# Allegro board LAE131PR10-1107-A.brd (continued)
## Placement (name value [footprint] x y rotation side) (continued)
RD14  -  [R_0402]  79.17 25.38 270 top
RD15  -  [R_0402]  170.27 27.54 90 top
RD16  -  [R_0402]  171.15 28.45 270 top
RD17  -  [R_0402]  172.02 28.45 270 top
RD18  -  [R_0402]  174.74 27.27 270 top
RD19  -  [R_0402]  88.61 62.61 0 bottom
RD20  -  [R_0402]  189.49 28.26 0 top
RD21  -  [R0402_0OHM]  190.4 27.37 180 top
RD22  -  [R0402_0OHM]  196.36 29.76 180 top
RD23  -  [R_0402]  195.43 28.87 0 top
RD24  -  [R_0402]  170.56 24.8 90 top
RD25  -  [R0402_0OHM]  169.67 25.83 270 top
RD26  -  [R0603_0OHM]  190.1 29.23 90 top
RD27  -  [R_0402]  80.06 25.38 270 top
RD28  -  [R_0402]  168.64 29.04 270 top
RD29  -  [R_0402]  167.1 28.12 90 top
RD30  -  [R_0402]  166.21 28.12 90 top
RD31  -  [R_0402]  162.37 28.12 90 top
RE5  -  [R_0402]  262.83 49.22 90 top
RE6  -  [R_0402]  279.4 61.5 180 top
RE8  -  [R_0402]  257 35.71 0 top
RE10  -  [R_0402]  274.94 35.21 270 top
RE11  -  [R_0402]  262.7 34.58 270 top
RE12  -  [R_0402]  275.96 34.23 0 top
RE13  -  [R_0402]  277.84 55.64 90 top
RE14  -  [R_0402]  278.74 56.57 270 top
RE15  -  [R_0402]  279.43 57.91 180 top
RE16  -  [R_0402]  278.51 58.82 0 top
RE17  -  [R_0402]  279.43 59.71 180 top
RE18  -  [R_0402]  278.49 60.6 0 top
RE20  -  [R_0402]  263.59 34.58 270 top
RE21  -  [R_0402]  255.02 34.58 90 top
RE25  -  [R_0402]  279.78 46.21 0 top
RE26  -  [R_0402]  281.64 45.27 90 top
RE30  -  [R0402_0OHM]  296.48 73.89 90 bottom
RE31  -  [R_0402]  250.99 30.17 90 top
RE32  -  [R0402_0OHM]  259.91 32.9 90 top
RE33  -  [R_0402]  250.05 31.15 90 top
RE34  -  [R0402_0OHM]  239.3 38.92 90 top
RE35  -  [R_0402]  273.22 49.14 90 top
RE37  -  [R_0402]  275.96 36.01 0 top
RE38  -  [R_0402]  272.33 49.14 90 top
RE43  -  [R_0402]  275.96 35.12 0 top
RE48  -  [R_0402]  184.05 69.75 90 bottom
RE51  -  [R_0402]  183.1 69.75 90 bottom
RE55  -  [R_0402]  261.81 34.58 270 top
RE56  -  [R_0402]  268.1 34.58 270 top
RE57  -  [R_0402]  261.37 32.24 270 top
RE58  -  [R_0402]  260.94 33.66 90 top
RE59  -  [R0402_0OHM]  271.5 51.1 90 top
RE60  -  [R_0402]  270.98 49.19 90 top
RE63  -  [R_0402]  265.86 51.39 0 top
RE64  -  [R_0402]  274.91 30.46 270 top
RE65  -  [R_0402]  264.94 51.39 180 top
RE67  -  [R_0402]  284.51 28.14 270 top
RE68  -  [R_0402]  281.4 30.28 90 top
RE69  -  [R_0402]  241.63 39.95 270 bottom
RE70  -  [R_0402]  240.17 36.24 180 bottom
RE71  -  [R_0402]  305.02 73.82 180 bottom
RE72  -  [R_0402]  301.22 76.52 270 bottom
RE73  -  [R_0402]  298.5 76.56 270 bottom
RE74  -  [R_0402]  297.58 76.55 270 bottom
RE75  -  [R_0402]  300.34 76.52 270 bottom
RE77  -  [R_0402]  263.01 52.3 90 top
RE79  -  [R_0402]  270.11 50.12 270 top
RE83  -  [R_0402]  267.85 49.22 90 top
RE84  -  [R_0402]  266.96 49.22 90 top
RE85  -  [R_0402]  266.07 49.22 90 top
RE86  -  [R_0402]  297.41 73.88 90 bottom
RE90  -  [R0402_0OHM]  241.1 35.31 90 bottom
RE91  -  [R_0402]  268.78 27.35 90 top
RE92  -  [R_0402]  262.74 28.4 0 top
RE93  -  [R_0201]  259.18 38.58 180 top
RE94  -  [R_0402]  255.46 39.93 90 top
RE95  -  [R_0402]  278.54 42.89 180 top
RE98  -  [R_0402]  278.65 35.65 180 top
RE274  -  [R_0402]  174.06 49.22 180 top
RE275  -  [R0402_0OHM]  174.98 48.32 180 top
RE280  -  [R_0402]  254.4 52.28 270 top
RE288  -  [R_0402]  268.66 51.02 90 top
RE290  -  [R0402_0OHM]  258.12 33.32 270 top
RE292  -  [R_0402]  255.3 51.35 90 top
RE300  -  [R_0402]  258.07 57.75 90 top
RE301  -  [R_0402]  261.95 49.74 90 top
RE302  -  [R_0402]  252.78 35.4 0 top
RE303  -  [R_0402]  252.78 34.45 0 top
RE304  -  [R_0402]  260.12 55.43 0 top
RE306  -  [R_0402]  299.39 76.52 270 bottom
RE308  -  [R_0402]  271.52 52.95 0 top
RE312  -  [R_0402]  274.94 32.95 270 top
RE313  -  [R_0402]  274.03 32.94 270 top
RE314  -  [R_0402]  265.99 32.66 0 top
RE318  -  [R0402_0OHM]  267.79 28.21 270 top
RE324  -  [R_0402]  265.95 28.23 270 top
RE337  -  [R_0402]  271.5 31.2 90 top
RE338  -  [R_0402]  278.53 41.99 180 top
RE339  -  [R_0402]  278.68 38.31 180 top
RE340  -  [R_0402]  276.58 31.99 0 top
RE341  -  [R_0402]  271.11 33.56 90 top
RE342  -  [R_0402]  269.37 32.31 0 top
RE343  -  [R_0402]  263.59 30.26 270 top
RE348  -  [R_0402]  240.21 39.85 270 top
RE349  -  [R_0402]  278.73 39.25 180 top
RE350  -  [R_0402]  254 40.16 270 top
RE360  -  [R0402_0OHM]  277.61 41.1 0 top
RE361  -  [R_0402]  262.7 31.44 90 top
RE362  -  [R_0402]  262.7 30.26 270 top
RE363  -  [R_0402]  269.03 34.58 270 top
RE364  -  [R0402_0OHM]  278.56 34.69 0 top
RE365  -  [R_0402]  250.13 41.37 0 top
RE366  -  [R_0402]  249.19 39.39 180 top
RE367  -  [R_0402]  233.89 38.89 180 top
RE368  -  [R_0402]  249.25 38.37 180 top
RE369  -  [R_0402]  235.66 38.58 180 top
RE370  -  [R_0402]  249.19 37.42 180 top
RE371  -  [R_0402]  235.54 37.24 180 top
RE372  -  [R_0402]  249.25 36.47 180 top
RE373  -  [R_0402]  233.76 37.24 180 top
RE374  -  [R_0402]  233.97 45.3 180 bottom
RE375  -  [R_0402]  226.94 37.19 0 bottom
RE376  -  [R_0402]  245.54 38.04 180 bottom
RE377  -  [R_0402]  247.27 36.56 270 top
RE505  -  [R_0402]  284.67 33.57 270 top
RE506  -  [R0402_0OHM]  280.34 40.67 90 top
RE507  -  [R_0402]  259.27 39.49 180 top
RE508  -  [R_0402]  259.01 32.04 0 top
RE512  -  [R_0402]  279.85 38.88 90 top
RE513  -  [R_0402]  280.74 38.88 90 top
RE514  -  [R_0402]  257.24 40.85 270 top
RE515  -  [R0402_0OHM]  256.34 40.85 270 top
RE524  -  [R_0402]  278.07 54.39 270 top
RE525  -  [R_0402]  277.13 54.39 270 top
RE526  -  [R_0402]  255.74 48.52 0 top
RE530  -  [R_0402]  257.58 86.07 0 top
RE532  -  [R_0402]  280.71 45.22 270 top
RE536  -  [R_0402]  237.12 40.67 90 top
RE537  -  [R_0402]  238.05 41.59 270 top
RE539  -  [R_0402]  276.66 51.15 0 top
RI13  -  [R_0402]  291.77 67.85 270 top
RI14  -  [R_0402]  294.79 71.62 180 top
RI27  -  [R_0402]  275.72 68.15 180 top
RI28  -  [R_0402]  275.72 69.03 180 top
RI29  -  [R_0402]  275.74 70.05 180 top
RI30  -  [R_0402]  275.74 70.92 180 top
RI47  -  [R_0402]  263.28 60.56 90 top
RI48  -  [R_0402]  264.16 60.56 90 top
RI49  -  [R_0402]  290.25 33.36 90 bottom
RI50  -  [R_0402]  291.14 33.36 90 bottom
RL1  -  [R_0402]  273.59 99.33 90 top
RL2  -  [R_0402]  272.06 99.38 90 top
RL3  -  [R0402_0OHM]  273.56 86.58 270 top
RL4  -  [R_0402]  270.54 92.08 270 top
RL5  -  [R_0402]  269.69 89.4 270 top
RL6  -  [R_0402]  268.8 89.4 270 top
RL7  -  [R0402_0OHM]  271.21 88.49 90 top
RL8  -  [R0603_0OHM]  270.64 87.34 180 top
RL9  -  [R_0402]  272.1 89.4 270 top
RL11  -  [R_0402]  277.55 88.93 0 top
RL12  -  [R_0402]  275.08 99.41 90 top
RL13  -  [R_0402]  281.89 89.35 0 top
RL14  -  [R_0402]  296.8 78.45 0 top
RL15  -  [R_0402]  303.15 90.8 0 top
RL16  -  [R_0402]  303.15 89.5 0 top
RL17  -  [R_0402]  303.19 83.25 0 top
RL18  -  [R_0402]  303.19 82.01 0 top
RL19  -  [R_0402]  295.28 82.52 180 top
RL20  -  [R_0402]  298.32 82.26 90 top
RL29  -  [R_0402]  295.35 86.56 180 top
RL30  -  [R_0402]  296.32 85.41 270 top
RL34  -  [R0402_0OHM]  278.46 88.04 180 top
RL70  -  [R_0402]  281.87 88.11 0 top
RL71  -  [R_0603]  281.97 90.48 0 top
RL72  -  [R_0603]  281.97 91.69 0 top
RL73  -  [R_0603]  281.97 92.89 0 top
RL74  -  [R_0603]  281.97 94.1 0 top
RL75  -  [R_0603]  281.97 95.31 0 top
RL76  -  [R_0603]  281.97 96.51 0 top
RL77  -  [R_0603]  281.97 97.72 0 top
RL78  -  [R_0603]  281.97 98.93 0 top
RN37  -  [R_0402]  24.78 16.92 180 top
RN99  -  [R0402_0OHM]  21.29 19.02 0 bottom
RN100  -  [R_0402]  41.02 19.28 90 top
RPC1  -  [RP_0804_8P4R]  176.59 84.44 0 bottom
RPC3  -  [RP_0804_8P4R]  147.04 99.8 90 bottom
RPC4  -  [RP_0804_8P4R]  163.03 86.28 0 bottom
RPE7  -  [RP_0804_8P4R]  303.82 75.66 90 bottom
RPE9  -  [RP_0804_8P4R]  276.67 46.87 0 top
RPE10  -  [RP_0804_8P4R]  276.67 49.85 0 top
RPE11  -  [RP_0804_8P4R]  269.76 30.92 270 top
RPE12  -  [RP_0804_8P4R]  274.95 43.69 0 top
RR3  -  [R_0402]  297.88 56.5 270 top
RR4  -  [R_0402]  292.56 50.39 180 top
RR5  -  [R0402_0OHM]  301.41 48.71 0 top
RR6  -  [R0402_0OHM]  301.42 50.48 0 top
RR7  -  [R0402_0OHM]  301.42 51.35 0 top
RR8  -  [R0402_0OHM]  301.87 52.23 0 top
RR9  -  [R0402_0OHM]  300.05 47.75 270 top
RR10  -  [R0402_0OHM]  300.94 47.73 270 top
RR19  -  [R_0402]  294.45 54.5 90 top
RT1  -  [R_0402]  23.88 72.99 90 bottom
RT2  -  [R_0402]  35.05 74.26 0 top
RT3  -  [R_0402]  35.05 73.25 0 top
RT4  -  [R_0402]  35.05 72.23 0 top
RT5  -  [R_0402]  33.24 82.35 0 bottom
RT6  -  [R_0402]  32.54 80.57 0 bottom
RT7  -  [R_0402]  32.54 81.46 0 bottom
RT8  -  [R_0402]  33.24 83.24 0 bottom
RT9  -  [R0402_0OHM]  35.97 75.28 180 top
RT10  -  [R_0402]  35.05 71.21 0 top
RT11  -  [R_0402]  24.68 80.08 270 bottom
RT12  -  [R_0402]  34.01 77.67 270 top
RT13  -  [R_0402]  34.9 77.67 270 top
RT14  -  [R_0402]  38.58 79.55 90 top
RT15  -  [R_0402]  38.58 79.55 90 bottom
RT16  -  [R_0402]  27.28 77.6 270 bottom
RT17  -  [R_0402]  25.63 77.6 270 top
RT18  -  [R_0402]  30.14 75.8 90 top
RT19  -  [R_0402]  31.35 75.8 90 top
RT20  -  [R_0402]  26.52 77.6 270 top
RT21  -  [R_0402]  21.13 83.45 180 top
RT22  -  [R_0402]  21.13 84.34 180 top
RT23  -  [R_0402]  28.42 81.6 270 bottom
RT24  -  [R_0402]  38.46 77.67 270 top
RT25  -  [R_0402]  25.5 77.6 270 bottom
RT26  -  [R_0402]  24.69 81.84 180 bottom
RT27  -  [R_0402]  24.61 77.6 270 bottom
RT28  -  [R_0402]  32.23 77.67 270 top
RT29  -  [R_0402]  34.14 84.12 90 bottom
RT30  -  [R_0402]  37.57 77.67 270 top
RT31  -  [R_0402]  18.96 83.55 90 top
RT32  -  [R_0402]  21.13 85.23 180 top
RT33  -  [R_0402]  27.47 77.6 270 top
RT34  -  [R_0402]  32.07 91 180 bottom
RT35  -  [R_0402]  35.03 84.12 90 bottom
RT36  -  [R_0402]  24.74 77.6 270 top
RT37  -  [R_0402]  36.01 81.83 270 top
RT38  -  [R_0402]  33.25 89.2 90 bottom
RT39  -  [R_0402]  27.08 84.84 0 bottom
RT40  -  [R0402_0OHM]  22.21 93.61 0 top
RT41  -  [R_0402]  26.27 90.88 0 bottom
RT42  -  [R_0402]  25.41 89.42 180 bottom
RT48  -  [R_0603]  23.62 73.12 270 top
RT49  -  [R_0603]  22.35 73.12 90 top
RT50  -  [R_0402]  28.12 50.43 180 top
RT51  -  [R_0402]  25.05 49.48 0 top
RT52  -  [R_0402]  25.05 50.43 0 top
RT53  -  [R_0402]  25.05 52.34 0 top
RT54  -  [R0402_0OHM]  28.12 51.45 180 top
RT55  -  [R0402_0OHM]  28.12 52.34 180 top
RT56  -  [R0402_0OHM]  25.05 51.38 0 top
RT57  -  [R0402_0OHM]  25.05 48.53 0 top
RT58  -  [R0402_0OHM]  39.21 66.22 180 bottom
RT59  -  [R0402_0OHM]  38.29 62.86 0 bottom
RT60  -  [R0402_0OHM]  34.06 61.32 180 top
RT63  -  [R0402_0OHM]  29.15 66.44 90 top
RT64  -  [R_0402]  33.15 59.54 0 top
RT65  -  [R_0402]  33.15 58.65 0 top
RT66  -  [R_0402]  38.86 63.72 90 top
RT67  -  [R_0402]  37.85 63.72 90 top
RT68  -  [R_0402]  33.15 60.43 0 top
RT69  -  [R_0402]  33.66 65.63 0 top
RT70  -  [R0402_0OHM]  30.1 69.2 270 top
RT71  -  [R_0402]  28.44 58.07 0 bottom
RT72  -  [R0402_0OHM]  26.81 55.77 90 top
RT73  -  [R0402_0OHM]  28.44 59.02 0 bottom
RT74  -  [R_0402]  27.56 57.36 90 bottom
RT75  -  [R_0402]  26.24 54.51 180 top
RT76  -  [R_0402]  25.12 62.59 180 bottom
RT81  -  [R_0402]  28.7 67.2 90 bottom
RT82  -  [R_0402]  27.82 67.2 90 bottom
RT83  -  [R0402_0OHM]  27.8 66.33 0 bottom
RT84  -  [R_0402]  26.04 66.31 90 bottom
RT85  -  [R_0402]  25.15 66.31 90 bottom
RT86  -  [R_0402]  28.64 56.69 270 top
RT87  -  [R0402_0OHM]  22.13 63.25 0 top
RT88  -  [R0402_0OHM]  22.13 62.36 0 top
RT89  -  [R_0402]  22.33 62.4 90 bottom
RT90  -  [R_0402]  23.23 62.39 90 bottom
RT92  -  [R0402_0OHM]  22.21 65.41 0 top
RT93  -  [R0402_0OHM]  22.21 66.3 0 top
RT95  -  [R_0402]  24.84 67.6 180 top
RT96  -  [R_0402]  25.71 67.6 0 top
RT97  -  [R_0402]  28.4 53.63 180 top
RT98  -  [R_0402]  26.24 53.63 180 top
RT99  -  [R0402_0OHM]  27.48 54.51 0 top
RT100  -  [R_0402]  26.93 66.31 90 bottom
RT101  -  [R_0402]  33.14 61.37 0 bottom
RT103  -  [R_0402]  23.65 56.94 180 top
RT104  -  [R0402_0OHM]  23.64 58.9 180 top
RT105  -  [R0402_0OHM]  23.64 57.82 180 top
RT106  -  [R_0402]  29.66 66.31 90 bottom
RT107  -  [R_0402]  33.14 62.26 0 bottom
RT108  -  [R0402_0OHM]  23.67 60.03 180 top
RT109  -  [R0402_0OHM]  23.67 60.92 180 top
RT110  -  [R_0402]  27.76 56.69 270 top
RT111  -  [R_0402]  18.93 94.91 0 top
RT120  -  [R0402_0OHM]  15.59 89.84 180 top
RT121  -  [R0402_0OHM]  15.59 88.95 180 top
RT122  -  [R0402_0OHM]  14.68 89.84 0 bottom
RT123  -  [R0402_0OHM]  14.68 88.95 0 bottom
RT124  -  [R_0402]  33.12 77.67 270 top
RT125  -  [R_0402]  35.79 77.67 270 top
RT126  -  [R_0402]  37.7 79.55 90 top
RT127  -  [R_0402]  37.7 79.55 90 bottom
RT128  -  [R_0402]  37.33 82.14 315 bottom
RT129  -  [R_0402]  29.31 81.6 270 bottom
RT336  -  [R_0402]  38.48 82.27 315 bottom
RT337  -  [R_0402]  30.2 81.6 270 bottom
RT338  -  [R_0402]  36.68 77.67 270 top
RT339  -  [R_0402]  33.14 60.48 0 bottom
RT341  -  [R0402_0OHM]  38.6 78.67 180 top
RT342  -  [R0402_0OHM]  38.6 78.67 180 bottom
RT371  -  [R_0402]  35.79 77.67 270 bottom
RT372  -  [R_0402]  26.39 77.6 270 bottom
RT377  -  [R_0402]  26.04 61.68 90 bottom
RT391  -  [R_0402]  150.55 102.51 90 bottom
RT392  -  [R0402_0OHM]  25.97 79.74 270 bottom
RT393  -  [R_0402]  17.03 94.34 180 top
RV1  -  [R_0402]  67.44 113.38 90 top
RV2  -  [R_0402]  66.92 116.97 0 top
RV3  -  [R_0402]  73.41 107.66 180 top
RV4  -  [R_0402]  59.31 104.49 0 top
RV5  -  [R_0402]  59.57 102.71 180 top
RV6  -  [R_0402]  98.94 109.75 90 top
RV7  -  [R_0402]  69.19 117.32 0 top
RV8  -  [R_0402]  93.03 116.34 270 top
RV10  -  [R_0402]  16.51 61.8 180 top
RV11  -  [R_0402]  16.51 62.68 180 top
RV12  -  [R_0402]  16.5 65.56 180 top
RV13  -  [R_0402]  16.5 66.44 180 top
RV14  -  [R_0402]  16.51 63.77 180 top
RV15  -  [R_0402]  16.51 64.65 180 top
RV16  -  [R_0402]  16.54 67.48 180 top
RV17  -  [R_0402]  16.54 68.36 180 top
RV18  -  [R_0402]  18.35 72.38 270 top
RV19  -  [R_0402]  19.32 71.47 90 top
RV20  -  [R_0402]  18.76 74.9 270 top
RV21  -  [R_0402]  14.57 74.66 90 top
RV22  -  [R_0402]  16.89 71.39 180 bottom
RV23  -  [R_0402]  16.89 70.16 180 bottom
RV26  -  [R_0402]  15.38 62.76 270 bottom
RV29  -  [R_0402]  15.36 66.49 270 bottom
RV32  -  [R_0402]  15.36 64.69 270 bottom
RV35  -  [R_0402]  15.37 68.29 270 bottom
RV70  -  [R_0402]  102.24 106.33 270 bottom
RV71  -  [R_0402]  104.05 106.33 270 bottom
RV73  -  [R_0402]  108.08 113 90 top
RV74  -  [R_0402]  103.71 112.64 0 top
RV76  -  [R_0402]  103.18 106.33 270 bottom
RV77  -  [R_0402]  104.98 106.33 270 bottom
RV79  -  [R_0402]  120.78 111.6 90 bottom
RV80  -  [R_0402]  123.57 111.52 90 bottom
RV81  -  [R_0402]  120.78 110.58 270 bottom
RV82  -  [R_0402]  121.77 110.53 0 bottom
RV83  -  [R_0402]  121.81 108.68 90 bottom
RV84  -  [R_0402]  122.81 109.19 0 bottom
RV85  -  [R_0402]  121.27 107.38 270 bottom
RV87  -  [R_0402]  115.22 105.08 0 top
RV88  -  [R_0402]  114.3 105.12 180 top
RV89  -  [R_0402]  110.53 104.9 270 bottom
RV90  -  [R_0402]  122.81 108.3 0 bottom
RV91  -  [R_0402]  122.81 107.41 0 bottom
RV93  -  [R_0402]  120.03 104.31 270 bottom
RV94  -  [R_0402]  119.05 104.3 270 bottom
RV95  -  [R_0402]  120.31 107.35 270 bottom
RV97  -  [R_0402]  109.56 104.92 270 bottom
RZ8  -  [R_0402]  283.36 29.84 180 bottom
RZ9  -  [R_0402]  283.38 28.92 180 bottom
RZ10  -  [R_0402]  258.08 28.06 0 bottom
RZ18  -  [R_0402]  248.68 25.35 0 top
RZ19  -  [R_0402]  248.69 24.45 0 top
RZ20  -  [R_0402]  164.21 78.37 270 bottom
RZ21  -  [R_0402]  166.94 78.37 270 bottom
RZ22  -  [R_0402]  250.28 27.18 270 top
RZ23  -  [R_0402]  249.58 23.42 0 top
RZ25  -  [R_0402]  310.7 7.49 90 top
RZ26  -  [R0402_0OHM]  165.15 77.31 270 bottom
RZ28  -  [R_0402]  314 5.95 90 top
RZ29  -  [R0402_0OHM]  166.03 77.31 270 bottom
RZ32  -  [R_0402]  241.6 45.02 90 bottom
RZ38  -  [R_0402]  303.75 58.4 180 top
RZ40  -  [R_0402]  284.41 77.95 0 top
RZ43  -  [R_0402]  263.37 73.48 180 top
RZ56  -  [R0402_0OHM]  280.29 47.4 0 top
RZ58  -  [R_0402]  174.77 81.82 180 bottom
RZ59  -  [R_0402]  174.89 83.98 180 bottom
RZ60  -  [R_0402]  174.89 85.76 180 bottom
RZ61  -  [R0402_0OHM]  174.89 84.87 180 bottom
RZ62  -  [R_0402]  170.88 80.31 270 bottom
RZ63  -  [R_0402]  174.89 86.65 180 bottom
RZ64  -  [R0402_0OHM]  204.01 34.96 180 top
RZ65  -  [R_0402]  204.01 33.95 180 top
RZ69  -  [R_0402]  173.93 88.5 270 bottom
RZ70  -  [R0402_0OHM]  302.01 58.41 180 top
RZ71  -  [R_0402]  302 59.3 180 top
RZ76  -  [R_0402]  273.75 77.63 270 top
RZ77  -  [R_0402]  274.63 77.63 270 top
RZ78  -  [R_0402]  284.78 49.44 180 top
RZ79  -  [R_0402]  284.79 50.4 180 top
RZ80  -  [R_0402]  280.27 50.7 0 top
RZ81  -  [R_0402]  280.35 51.61 0 top
RZ85  -  [R0402_0OHM]  278.97 27.91 180 top
RZ87  -  [R0402_0OHM]  258.07 27.16 0 bottom
RZ89  -  [R0402_0OHM]  163.69 85.18 0 bottom
RZ111  -  [R_0402]  161.67 80.56 270 bottom
RZ112  -  [R_0402]  169.04 79.39 90 bottom
RZ113  -  [R_0402]  162.77 85.18 180 bottom
RZ114  -  [R_0402]  262.49 24.68 90 top
RZ116  -  [R_0402]  168.37 77.95 270 top
RZ117  -  [R_0402]  169.24 77.95 270 top
RZ119  -  [R_0402]  177.8 44.67 90 top
RZ120  -  [R0402_0OHM]  180.08 47.69 0 top
RZ128  -  [R_0201]  282.75 69.7 270 bottom
RZ129  -  [R_0201]  282.79 70.3 0 bottom
RZ130  -  [R_0201]  282.79 70.9 0 bottom
RZ131  -  [R_0402]  273.21 64.85 0 top
RZ132  -  [R_0402]  276.1 63.25 90 top
RZ151  -  [R_0603]  131.75 94.16 0 bottom
RZ320  -  [R_0402]  134.38 104.11 180 bottom
RZ326  -  [R_0402]  267.97 65.96 270 top
RZ334  -  [R_0402]  305.05 43.58 180 bottom
RZ335  -  [R_0402]  305.05 41.49 180 bottom
RZ345  -  [R0402_0OHM]  168.15 63.59 180 top
RZ346  -  [R0402_0OHM]  249.54 22.5 0 top
RZ347  -  [R0402_0OHM]  252.5 26.04 90 top
RZ361  -  [R_0402]  313.13 5.3 180 top
RZ362  -  [R_0402]  169.93 79.39 90 bottom
RZ363  -  [R0402_0OHM]  159.64 82.4 270 bottom
SW1  -  [SW_SS3-CMFTQR9_3P]  239.57 49.76 30 bottom
SW3  -  [SW_SKRBAAE010_4P]  314.79 104.54 0 top
T1  -  [TPC12]  118.68 84.23 0 top
T2  -  [TPC12]  117.35 84.11 0 top
T3  -  [TPC12]  112.33 60.48 180 bottom
T4  -  [TPC12]  110.97 60.24 180 bottom
T5  -  [TPC12]  115.4 71.52 0 top
T6  -  [TPC12]  114.51 70.33 0 top
T9  -  [TPC12]  100.54 96.12 180 bottom
T10  -  [TPC12]  116.75 92.75 180 bottom
T12  -  [TPC12]  90.81 61.69 180 bottom
T13  -  [TPC12]  92.08 62.2 180 bottom
T15  -  [TPC12]  139.1 74.29 0 top
T16  -  [TPC12]  90.87 63.02 180 bottom
T17  -  [TPC12]  89.16 64.1 180 bottom
T50  -  [TPC12]  88.59 22.97 0 top
T51  -  [TPC12]  90.67 31.96 0 top
T54  -  [TPC12]  169.1 26.83 0 top
T55  -  [TPC12]  168.25 35.32 0 top
T88  -  [TPC12]  274.45 98.55 0 top
T89  -  [TPC12]  272.75 98.49 0 top
T113  -  [TPC12]  87.7 64.42 180 bottom
T114  -  [TPC12]  90.68 64.48 180 bottom
T115  -  [TPC12]  138.09 70.12 0 top
T120  -  [TPC12]  138.26 81.71 0 top
T122  -  [TPC12]  127.66 82.94 0 top
T123  -  [TPC12]  127.07 74.58 0 top
T126  -  [TPC12]  151.51 63.28 180 bottom
T127  -  [TPC12]  168.44 63.34 180 bottom
T128  -  [TPC12]  152.34 69.42 180 bottom
T129  -  [TPC12]  151.83 70.61 180 bottom
T130  -  [TPC12]  171.16 63.26 180 bottom
T132  -  [TPC12]  104.32 61.51 0 top
T219  -  [TPC12]  26.02 68.14 180 bottom
T220  -  [TPC12]  24.73 68.15 180 bottom
T225  -  [TPC12]  280.09 63.71 0 top
T258  -  [TPC12]  173.9 63.32 180 bottom
T267  -  [TPC12]  275.31 61.56 0 top
T268  -  [TPC12]  172.62 63.32 180 bottom
T269  -  [TPC12]  150.75 92.93 180 bottom
T283  -  [TPC12]  166.97 87.92 180 bottom
TL1  -  [MHPC_NS692417_24P]  294.32 79.46 90 bottom
UA1  -  [ALC3246-CG_MQFN48_6X6]  297.26 34.62 0 top
UC1  -  [SKL-U_BGA_1356P-T]  145.51 88.61 0 bottom
UC5  -  [W25Q128FVSIQ_SO8]  187.67 90.98 270 bottom
UC6  -  [W25Q128FVSIQ_SO8]  187.68 84.84 270 bottom
UC7  -  [TC7SH08FU_SSOP5]  175.22 93.87 270 bottom
UC8  -  [74CBTLV3126BQ_DHVQFN14_2P5X3-S]  65.09 101.16 180 top
UC12  -  [74AHC1G09GW_TSSOP5]  148.43 101.11 0 bottom
UD1  -  [74AUP1G07GW_TSSOP5]  85.5 61.31 90 bottom
UE1  -  [MEC5105_WFBGA_169P]  262.42 36.79 90 top
UE2  -  [IT8010FN-BX-R_QFN20_4X4]  276.38 57.21 180 top
UE3  -  [TC7SH08FU_SSOP5]  259.07 52.46 0 top
UE4  -  [74AUP1G07GW_TSSOP5]  259.2 56.77 0 top
UE5  -  [TC7SH08FU_SSOP5]  257.65 53.09 180 top
UE6  -  [74AUP1G07GW_TSSOP5]  278.29 29.69 90 top
UE7  -  [AP2112K-3P3TRG1_SOT23-5]  241.39 41.81 270 top
UE9  -  [W25Q80DVSSIG_SO8]  235.69 36.3 180 bottom
UI1  -  [SY6288D20AAC_SOT23-5]  25.19 28.99 90 bottom
UI2  -  [SY6288D20AAC_SOT23-5]  28.77 45.06 0 top
UI3  -  [SLGC55544CVTR_TQFN16_3X3]  293.09 69.35 270 top
UL1  -  [WGI217LM-QPN9-A2_QFN48_6X6-S]  273.1 91.44 0 top
UL2  -  [TC7SH08FU_SSOP5]  293.26 85.41 270 top
UR1  -  [RTS5242-GR_QFN32_4X4-S]  295.8 53.35 0 top
UT1  -  [ALPINE-RIDGE_BGA_337P]  23.87 81.42 90 top
UT2  -  [W25Q80DVSSIG_SO8]  33.4 73.37 270 bottom
UT5  -  [TPS65982_BGA_96P]  30.76 63.81 270 top
UT6  -  [W25Q80DVSSIG_SO8]  21.78 48.93 90 bottom
UT7  -  [AP2112K-3P3TRG1_SOT23-5]  18.16 96.03 0 top
UT8  -  [AP2204R-5P0TRG1_SOT89-3]  40.57 21.56 270 bottom
UV2  -  [AP2330W-7_SC59-3]  18.38 74.95 180 bottom
UV7  -  [PS8338BQFN60GTR-A0_QFN60_5X9-S]  117.73 106.93 180 bottom
UV24  -  [G524B1T11U_SOT23-5]  71.25 111.85 180 top
UZ1  -  [APX8131AI-TRG_SOT23-3]  156.53 114.59 0 top
UZ2  -  [TPS22966DPUR_SON14_2X3-S]  300.24 60.71 0 top
UZ3  -  [TPS22966DPUR_SON14_2X3-S]  201.4 33.89 90 top
UZ4  -  [TPS22966DPUR_SON14_2X3-S]  286.55 79.71 270 top
UZ5  -  [TPS22966DPUR_SON14_2X3-S]  296.65 22.87 180 top
UZ6  -  [TC7SH08FU_SSOP5]  243.58 32.27 180 bottom
UZ8  -  [AOZ1336_DFN8_2X2]  166.11 65.76 0 top
UZ10  -  [TC7SH08FU_SSOP5]  251.53 33.37 270 top
UZ12  -  [NPCT650JB2YX_QFN32_5X5]  167.06 82.55 0 bottom
UZ19  -  [TPS22961DNYR_WSON8]  130.33 103.88 0 bottom
UZ21  -  [TPS22961DNYR_WSON8]  131.61 107.24 270 bottom
UZ26  -  [TPS22961DNYR_WSON8]  179.05 43.53 0 top
UZ34  -  [TC7SH08FU_SSOP5]  187.76 49.08 0 top
UZ35  -  [TC7SH08FU_SSOP5]  135.21 105.86 180 bottom
YC1  -  [Y_X3G024000DC1H_4P]  127.3 98.33 180 bottom
YC2  -  [Y_9H03200042_2P]  153.06 75.76 180 top
YE1  -  [Y_X1A000141000200_2P]  255.64 30.72 90 top
YL1  -  [Y_7V25000034_4P]  279.78 85.69 180 top
YT1  -  [Y_7V25000034_4P]  21.67 94.84 0 top

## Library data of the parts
CA1-CA6 CA12 CA13 CA19 CA22-CA24 CA27 CA28 CA33 CA35 CA41 CA54 CA62-CA69 CA72 CC7 CC8 CC21-CC27 CC32 CC33 CC176-CC180 CC183 CC184 CC187 CC195 CC199 CC202-CC209 CC211 CC212 CC215-CC218 CC222 CC224 CC250-CC253 CC264-CC266 CC269 CC288-CC293 CC297 CC300-CC308 CC310 CC312 CC316 CC318-CC326 CC331-CC333 CD9-CD16 CD18 CD19 CD23-CD27 CD29 CD31 CD41-CD48 CD50 CD51 CD55-CD59 CD61 CD62 CE1-CE6 CE8 CE10 CE12 CE14 CE24 CE26-CE31 CE35-CE40 CE46 CE47 CE52-CE54 CE57 CE59-CE62 CE500 CE503 CI4 CI5 CI13 CI16 CI27-CI31 CI43-CI48 CL1 CL2 CL5 CL6 CL13 CL14 CL18 CL29 CL30 CN60 CN69-CN72 CR1 CR4 CR11-CR15 CR21 CR22 CR25-CR28 CT20 CT21 CT44-CT47 CT59 CT60 CT67 CT70-CT74 CT83 CT85-CT87 CT89 CT90 CT92 CT93 CT189 CT190 CV1-CV10 CV13 CV14 CV17-CV25 CV31-CV38 CV81 CV82 CV96 CV145-CV150 CV152 CV153 CV156 CV157 CZ3 CZ12-CZ15 CZ17-CZ19 CZ21 CZ23-CZ25 CZ28 CZ29 CZ33-CZ41 CZ56-CZ63 CZ69 CZ71-CZ73 CZ75 CZ80 CZ81 CZ83 CZ100 CZ102 CZ104 CZ105 CZ109 CZ110 CZ113 CZ114 CZ117 CZ118 CZ121 CZ124 CZ126 CZ127 CZ197 CZ198 PC1 PC2 PC9 PC10 PC100 PC103 PC113 PC115 PC116 PC127 PC128 PC202 PC203 PC206-PC208 PC216-PC218 PC221 PC222 PC301 PC303 PC307 PC401 PC402 PC408-PC411 PC417-PC420 PC503 PC505 PC506 PC513 PC515 PC601 PC602 PC605 PC613 PC614 PC616-PC621 PC624-PC633 PC635-PC647 PC649-PC654 PC659-PC661 PC669 PC677 PC679-PC681 PC685-PC688 PC902 PC903 PC925-PC929 PC932 PC933 PC937-PC939 PC942-PC947 PC949 PC950 PC1201 PC1203-PC1217 PC1286 PC1301 PC1302 PC1308-PC1311 PC1317-PC1320 = C_0402
CA7 CA8 CA10 CA45 CA47 CA55 CA57 CA60 CC9 CC10 CC28-CC30 CC213 CC214 CC223 CC270 CC281 CC313 CC314 CD28 CD32 CD60 CE11 CE13 CE15 CE18-CE23 CE25 CI3 CI7 CI10 CI12 CI17 CI19 CL3 CL7-CL11 CL15-CL17 CL19-CL21 CN61 CN62 CR2 CR3 CR6 CR7 CR17 CR19 CT1-CT19 CT25-CT43 CT48-CT54 CT61-CT64 CT80 CT81 CT88 CT95-CT102 CT123-CT130 CT168-CT177 CT201-CT204 CV12 CV39 CV40 CV83-CV95 CZ1 CZ2 CZ30 CZ31 CZ50 CZ51 CZ53 CZ54 CZ64 CZ66-CZ68 CZ82 CZ90-CZ94 CZ101 CZ103 CZ106 CZ111 CZ112 CZ115 CZ116 CZ119 CZ120 CZ122 CZ125 CZ128 PC1030-PC1056 PC1083-PC1099 PC1125 PC1126 PC1147-PC1153 PC1164 = C_0201
CA9 CA25 CA29 CA31 CA43 CA44 CA46 CA48 CA49 CA51-CA53 CA56 CA58 CA59 CA61 CC279 CC280 CC294-CC296 CD1-CD8 CD20-CD22 CD33-CD40 CD52-CD54 CE16 CE17 CE32 CI6 CI11 CI33 CI34 CL4 CL12 CN63 CN64 CR5 CR18 CR20 CT55-CT57 CT82 CT84 CT91 CT94 CV11 CV15 CV16 CV41 CZ20 CZ27 CZ32 CZ52 CZ55 PC3-PC7 PC11 PC102 PC104 PC111 PC112 PC114 PC119 PC125 PC126 PC204 PC205 PC209-PC214 PC219 PC302 PC304-PC306 PC308-PC313 PC403 PC404 PC406 PC407 PC412 PC413 PC415 PC416 PC422 PC424 PC501 PC502 PC504 PC514 PC516 PC603 PC604 PC611 PC622 PC655 PC662 PC663 PC670 PC671 PC678 PC930 PC931 PC934 PC940 PC941 PC1001-PC1029 PC1057-PC1061 PC1064-PC1082 PC1100-PC1103 PC1129-PC1146 PC1170-PC1199 PC1202 PC1305-PC1307 PC1314-PC1316 = C_0603
CC210 CC220 CC221 CC225 CC226 CL28 CT68 CT69 CT75-CT78 PC8 PC105-PC110 PC117 PC118 PC120-PC124 PC129 PC130 PC200 PC201 PC608 PC612 PC656-PC658 PC664 PC665 PC672 PC673 PC682-PC684 PC904-PC906 PC911 PC913-PC920 PC935 PC936 PC1303 PC1304 PC1312 PC1313 = C_0805
CD17 CD49 PC1062 PC1127 PC1128 = C_D3
CI1 CI8 CI14 = C_1206
CI32 CZ26 PC909 PC910 PC951 = C_B2
CL22 = C_1808
CLIP1-CLIP12 = EMIST_SUL-12A2M_1P
CMOS1 = SHORTPADS-NPM: User Part Number: PART#
DA1-DA3 DA6 DA7 = L03ESDL5V0CC3-2_SOT23-3
DA8 DE1 DZ1 DZ2 DZ5-DZ7 = RB751S40T1G_SOD523-2
DI1 DI4 DI6 = L05ESDL5V0NA-4_SLP2510P8-10-9
DI2 DI3 DI5 DV4 = AZC199-02SPR7G_SOT23-3
DT1-DT3 = 1N4148WS-7-F_SOD323-2
DT4 = L30ESD24VC3-2_SOT23-3
DT5-DT20 DV7 DV8 = ESD8011MUT5G_X3DFN2-2-S
DV1-DV3 PD905 PD1801 = BAT54CW_SOT323-3
FD1-FD4 = FIDUCIAL_C40M80
H1-H4 = H_3P3
H5 H6 = H_1P0N
H7 H8 = H_3P2
H9 H10 H12 H14 H15 H19 H21 H22 = H_2P3-G
H17 H18 H30 H31 = H_3P7-G
H23 H26 = H_2P5-G
H24 H25 = H_4P7X3P7-G
H27 = H_2P5N
H28 = H_5P0X4P0-G
H29 = H_3P5X2P5N
H34 = H_3P5X2P5-G
JAPS1 = ACES_50506-01841-P01_18P
JDB1 = ACES_50506-00641-P01_6P
JDEG1 = HB_A531015-SCHR21_10P
JDIMM1 JDIMM2 = LCN_DAN05-Q0406-0103_260P
JEDP1 = ACES_50398-04041-001_40P
JESPI = ACES_50506-01041-P01_10P
JFAN1 JSPK1 = ACES_50271-0040N-001_4P
JHDMI1 = ACON_HMRBL-A41L0F_19P-T
JHP1 = SINGA_2SJ3095-085111F_6P
JIR1 = E-T_4251K-F06N-40L_6P
JKBTP1 = CVILU_CF5020FD0RK-05-NH_20P-T
JLED1 JTS1 = ACES_50209-0060N-P01_6P
JLOM1 = SANTA_130470-19_13P-T
JNGFF1 = LCN_DAN05-67306-0100_75P
JNGFF2 = BELLW_80149-3221_67P
JNGFF3 = LOTES_APCI0170-P001A_75P
JRTC1 = ACES_50271-0020N-001_2P
JSD1 = T-SOL_158-1240902600_23P-T
JSIM1 = JAE_SF51S006V4DR1000Q_8P
JSPI1 = E-T_6705K-Y20N-00L_20P
JTAG1 = SHORTPADS: User Part Number: PART#
JUART1 = CVILU_CI1804M1VRA-NH_4P
JUSB1 = ACON_TCRA2-9U1U93_9P-T
JUSB2 JUSB3 = C-K_26230A-8K1A-02_9P-T
JUSBC1 = JAE_DX07B024XJ1R1300_24P
JUSH1 = CVILU_CF5026FD0RK-05-NH_26P-T
JXDP1 = E-T_6601K-Y61N-04L_61P
LA5 LA12 LA14 = MURAT_BLM15PX600SN1D_2P
LA6-LA11 = MURAT_BLM15PX330SN1D_2P
LA13 = TAI-T_HCB2012VF-601T20_2P
LC1 LC2 = MURAT_BLM15GA750SN1D_2P
LED3 = LED_LTW-C193DC-C_2P
LI3 LI4 LI7 LV27 LZ1 = PANAS_EXC24CQ900U_4P
LI8 LI9 LI16 LI17 = INPAQ_HCM2012GA900AE_4P
LL1 = TAIYO_BRC2012T4R7MD_2P
LT1 = MAG_MND-04ABIR60M-XGL_2P
LT2 = MURAT_LQM18NN1R0K00D_2P
LV1 = MURAT_BLM15PX221SN1D_2P
LV3 LV6 LV9 LV12 = TAIYO_MCF12102G900-T_4P
LV31-LV38 = MURAT_LQG15HN12NJ02D_2P
PBATT1 = DEREN_40-42251-01001RHF_10P-T
PC606 = C_D
PC1063 PC1165 = C_D2
PD1 PD2 = TVNST52302AB0_SOT523-3
PD3 = DB3J315E0L_SMINI3-F2-B3
PD4 = PESD5V0U2BT_SOT23-3
PD5 PD1202 = PDS5100H-13_POWERDI5-3
PD100 PD903 = RB520SM-30T2R_EMD2-2
PD901 PD904 PD1205 = SDMK0340L-7-F_SOD323-2
PH601-PH605 PR1-PR8 PR10-PR12 PR14-PR18 PR24 PR27 PR28 PR102 PR103 PR107 PR108 PR113 PR116 PR117 PR204-PR207 PR209 PR212 PR302 PR306-PR308 PR310 PR311 PR403 PR404 PR407 PR408 PR410-PR422 PR424 PR427 PR428 PR501 PR505 PR506 PR514-PR517 PR601 PR604 PR605 PR608 PR610-PR613 PR615 PR617 PR618 PR621-PR623 PR626 PR628-PR636 PR638-PR654 PR656-PR658 PR662 PR666 PR670 PR673 PR677 PR678 PR680 PR681 PR909 PR910 PR915 PR918 PR919 PR925 PR927 PR930-PR933 PR937 PR938 PR940 PR944 PR945 PR948 PR950 PR953 PR1201-PR1203 PR1205-PR1210 PR1212-PR1214 PR1217 PR1219 PR1222 PR1224 PR1226-PR1237 PR1239 PR1240 PR1246-PR1249 PR1251-PR1255 PR1258-PR1261 PR1302 PR1304 PR1306-PR1313 PR1316-PR1318 PR1320-PR1326 RA5-RA9 RA12-RA14 RA17 RA18 RA44 RA45 RA50-RA53 RA57-RA61 RC1-RC7 RC10-RC17 RC19-RC23 RC25 RC27-RC32 RC39 RC42-RC48 RC50-RC52 RC54 RC56 RC57 RC59 RC60 RC65 RC67-RC69 RC71-RC75 RC77-RC84 RC86-RC96 RC109 RC110 RC112-RC115 RC120-RC124 RC126 RC128-RC141 RC152 RC153 RC157 RC161 RC163 RC165-RC168 RC175-RC178 RC183 RC184 RC186 RC187 RC189 RC190 RC211 RC215 RC217-RC220 RC222-RC225 RC227 RC234 RC237 RC239-RC241 RC243 RC267 RC268 RC272 RC278 RC279 RC282 RC283 RC287 RC288 RC291 RC292 RC297 RC298 RC311 RC313 RC316-RC319 RC323 RC324 RC330 RC331 RC338 RC344-RC349 RC362 RC363 RC366-RC369 RC371 RC372 RC387 RC400-RC403 RC405 RC407-RC414 RD4 RD6 RD8 RD11 RD14-RD20 RD23 RD24 RD27-RD31 RE5 RE6 RE8 RE10-RE18 RE20 RE21 RE25 RE26 RE31 RE33 RE35 RE37 RE38 RE43 RE48 RE51 RE55-RE58 RE60 RE63-RE65 RE67-RE75 RE77 RE79 RE83-RE86 RE91 RE92 RE94 RE95 RE98 RE274 RE280 RE288 RE292 RE300-RE304 RE306 RE308 RE312-RE314 RE324 RE337-RE343 RE348-RE350 RE361-RE363 RE365-RE377 RE505 RE507 RE508 RE512-RE514 RE524-RE526 RE530 RE532 RE536 RE537 RE539 RI13 RI14 RI27-RI30 RI47-RI50 RL1 RL2 RL4-RL6 RL9 RL11-RL20 RL29 RL30 RL70 RN37 RN100 RR3 RR4 RR19 RT1-RT8 RT10-RT39 RT41 RT42 RT50-RT53 RT64-RT69 RT71 RT74-RT76 RT81 RT82 RT84-RT86 RT89 RT90 RT95-RT98 RT100 RT101 RT103 RT106 RT107 RT110 RT111 RT124-RT129 RT336-RT339 RT371 RT372 RT377 RT391 RT393 RV1-RV8 RV10-RV23 RV26 RV29 RV32 RV35 RV70 RV71 RV73 RV74 RV76 RV77 RV79-RV85 RV87-RV91 RV93-RV95 RV97 RZ8-RZ10 RZ18-RZ23 RZ25 RZ28 RZ32 RZ38 RZ40 RZ43 RZ58-RZ60 RZ62 RZ63 RZ65 RZ69 RZ71 RZ76-RZ81 RZ111-RZ114 RZ116 RZ117 RZ119 RZ131 RZ132 RZ320 RZ326 RZ334 RZ335 RZ361 RZ362 = R_0402
PJP1 PJP2 PJP4 PJP6 PJP7 PJP12 PJP15 PJP16 PJP18-PJP22 PJP35 PJP37 PJP38 PJP42 PJP201 PJP391 PJP403 PJP404 PJP501 PJP502 PJP505 PJP506 PJP603 PJP1301 PJP1304 = JUMP_43X39
PJP3 PJP31 PJP39 PJP41 PJP102 PJP103 PJP200 PJP302 PJP601 PJP1202 = JUMP_43X118
PJP5 PJP8 PJP14 PJP17 PJP36 PJP40 PJP100 PJP101 PJP202 PJP301 PJP401 PJP402 PJP602 PJP1302 PJP1303 = JUMP_43X79
PJP901 = JUMP_43X118-NPM
PJPDC1 = CVILU_CI0805M1HRC-NH_5P-T
PL1 PL2 PL4 = TAIYO_FBMJ4516HS720NT_2P
PL3 = MURAT_BLM15AG102SN1D_2P
PL100 PL101 = CYNTE_PCMC063T-1R5MN_2P
PL201 PL902 = CYNTE_PCMB063T-1R0MS_2P
PL301 = MAG_MMD-05CZ-R68M-X2L_2P
PL402 PL404 PL501 PL1301 PL1302 = MAG_MLV-FY12N1R0M-O1L_2P
PL602 = 9A_Z80_1812_2P-NPM
PL610 PL612 PL613 = MAG_MMD06CZER15MG_4P
PL614 = MAG_MMD05CZR47M_4P
PL901 = MAGLA_MMD-05CZ-1R0M-M7L_2P
PL1201 PL1202 = 5A_Z120_0805_2P
PQ1 PQ1201 PQ1204 PQ1209 PQ1214 QC2 QE2 QE13 QL1 QL2 QV3 QZ2 QZ7 = DMN65D8LDW-7_SOT363-6
PQ2 = FDV301N-G_SOT23-3
PQ3 = MMST3904-7-F_SOT323-3
PQ4 PQ9 PQ906 PQ1202 PQ1206 PQ1213 = AON7409_DFN8-5
PQ5 PQ1203 PQ1215 = NTR4502PT1G_SOT23-3
PQ6-PQ8 PQ909 PQ1205 PQ1212 PQ1216 = DMN65D8LW-7_SOT323-3
PQ501 = AON7934_DFN3X3A8-10
PQ904 PQ905 = AON6992_DFN5X6D-8-7
PQ1207 PQ1208 PQ1210 PQ1211 QT1 = DMN66D0LDW-7_SOT363-6
PR13 PR916 = R_0805
PR19-PR23 PR25 PR26 PR29 PR104 PR105 PR114 PR119 PR120 PR208 PR210 PR312 PR402 PR406 PR423 PR425 PR426 PR504 PR513 PR602 PR603 PR606 PR614 PR616 PR620 PR625 PR659 PR664 PR671 PR679 PR920 PR922 PR926 PR928 PR929 PR934-PR936 PR939 PR941 PR942 PR946 PR947 PR949 PR951 PR960 PR1211 PR1215 PR1216 PR1218 PR1220 PR1221 PR1223 PR1225 PR1238 PR1241-PR1245 PR1250 PR1257 PR1301 PR1303 PR1314 PR1315 RA35-RA37 RA48 RA54-RA56 RC33-RC38 RC40 RC41 RC62 RC170 RC171 RC173 RC212 RC214 RC221 RC228-RC231 RC235 RC244 RC290 RC295 RC296 RC300-RC308 RC325 RC328 RC337 RC373-RC378 RD5 RD7 RD9 RD12 RD21 RD22 RD25 RE30 RE32 RE34 RE59 RE90 RE275 RE290 RE318 RE360 RE364 RE506 RE515 RL3 RL7 RL34 RN99 RR5-RR10 RT9 RT40 RT54-RT60 RT63 RT70 RT72 RT73 RT83 RT87 RT88 RT92 RT93 RT99 RT104 RT105 RT108 RT109 RT120-RT123 RT341 RT342 RT392 RZ26 RZ29 RZ56 RZ61 RZ64 RZ70 RZ85 RZ87 RZ89 RZ120 RZ345-RZ347 RZ363 = R0402_0OHM
PR100 PR111 PR203 PR304 PR914 PR943 R274 RA3 RC143 RC169 RC216 RC232 RC299 RC309 RC310 RD10 RD26 RL8 = R0603_0OHM
PR106 PR112 PR202 PR303 PR627 PR663 PR669 PR676 PR923 PR924 = R_1206
PR405 PR409 PR502 PR619 PR624 PR660 PR661 PR665 PR667 PR668 PR672 PR674 PR675 PR921 PR1305 PR1319 RL71-RL78 RT48 RT49 RZ151 = R_0603
PR901 PR917 = R_1206_4P-D
PRP1 RPC1 RPC3 RPC4 RPE7 RPE9-RPE12 = RP_0804_8P4R
PT1 T1-T6 T9 T10 T12 T13 T15-T17 T50 T51 T54 T55 T88 T89 T113-T115 T120 T122 T123 T126-T130 T132 T219 T220 T225 T258 T267-T269 T283 = TPC12
PU1 PU903 PU1200 UC7 UE3 UE5 UL2 UZ6 UZ10 UZ34 UZ35 = TC7SH08FU_SSOP5
PU2 = AP2204RA-3P3TRG1_SOT89-3
PU100 = SY8288BRAC_QFN20_3X3
PU102 = SY8288CRAC_QFN20_3X3
PU200 = SY8210AQVC_QFN19_4X3
PU301 = SYX196DQNC_QFN10_3X3
PU401 PU402 PU1301 PU1302 = SY8057QDC_QFN16_3X3
PU501 = RT8097ALGE_SOT23-6
PU503 = AP7361C-FGE-7_U-DFN3030-8_3X3
PU602 = ISL62883CHRTZ-T_TQFN40_5X5-S
PU610 PU612 PU613 = CSD97374CQ4M_SON8_3P5X4P5
PU614 = ISL95808HRZ-TS2378_DFN8_2X2-S
PU901 = ISL88738HRTZ-T_TQFN32_4X4
PU1201 = LM393DGKR_VSSOP8
QE3-QE7 = MMBT3904WT1G_SC70-3
QE11 QE12 QR1 QV2 QV4 QV5 QV7 = L2N7002WT1G_SC-70-3
QV1 = AO6405_TSOP6
QV8 QZ1 QZ9 = LP2301ALT1G_SOT23-3
QZ3 = DDTA114EUA-7-F_SOT323-3
RE93 RZ128-RZ130 = R_0201
SW1 = SW_SS3-CMFTQR9_3P
SW3 = SW_SKRBAAE010_4P
TL1 = MHPC_NS692417_24P
UA1 = ALC3246-CG_MQFN48_6X6
UC1 = SKL-U_BGA_1356P-T
UC5 UC6 = W25Q128FVSIQ_SO8
UC8 = 74CBTLV3126BQ_DHVQFN14_2P5X3-S
UC12 = 74AHC1G09GW_TSSOP5
UD1 UE4 UE6 = 74AUP1G07GW_TSSOP5
UE1 = MEC5105_WFBGA_169P
UE2 = IT8010FN-BX-R_QFN20_4X4
UE7 UT7 = AP2112K-3P3TRG1_SOT23-5
UE9 UT2 UT6 = W25Q80DVSSIG_SO8
UI1 UI2 = SY6288D20AAC_SOT23-5
UI3 = SLGC55544CVTR_TQFN16_3X3
UL1 = WGI217LM-QPN9-A2_QFN48_6X6-S
UR1 = RTS5242-GR_QFN32_4X4-S
UT1 = ALPINE-RIDGE_BGA_337P
UT5 = TPS65982_BGA_96P
UT8 = AP2204R-5P0TRG1_SOT89-3
UV2 = AP2330W-7_SC59-3
UV7 = PS8338BQFN60GTR-A0_QFN60_5X9-S
UV24 = G524B1T11U_SOT23-5
UZ1 = APX8131AI-TRG_SOT23-3
UZ2-UZ5 = TPS22966DPUR_SON14_2X3-S
UZ8 = AOZ1336_DFN8_2X2
UZ12 = NPCT650JB2YX_QFN32_5X5
UZ19 UZ21 UZ26 = TPS22961DNYR_WSON8
YC1 = Y_X3G024000DC1H_4P
YC2 = Y_9H03200042_2P
YE1 = Y_X1A000141000200_2P
YL1 YT1 = Y_7V25000034_4P

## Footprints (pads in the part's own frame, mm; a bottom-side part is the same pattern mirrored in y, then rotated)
1N4148WS-7-F_SOD323-2
  rect 1.346x0.66 smd: 1(0,0) 2(2.4,0)
5A_Z120_0805_2P
  rect 0.991x0.991 smd: 1(0,0) 2(2,0)
9A_Z80_1812_2P-NPM
  rect 1.803x3.404 smd: 1(0,0) 2(3.8,0)
74AHC1G09GW_TSSOP5
  oval 0.381x1.346 smd: 1(0,0) 2(0.65,0) 3(1.3,0) 4(1.3,1.79) 5(0,1.79)
74AUP1G07GW_TSSOP5
  oval 0.381x1.346 smd: 1(0,0) 2(0.65,0) 3(1.3,0) 4(1.3,1.79) 5(0,1.79)
74CBTLV3126BQ_DHVQFN14_2P5X3-S
  oval 1.041x0.254 smd: 1(0,0) 7(2.95,0) 8(2.95,0.5) 14(0,0.5)
  oval 0.254x1.041 smd: 2(0.475,-0.975) 3(0.975,-0.975) 4(1.475,-0.975) 5(1.975,-0.975) 6(2.475,-0.975) 9(2.475,1.475) 10(1.975,1.475) 11(1.475,1.475) 12(0.975,1.475) 13(0.475,1.475)
  rect 1.499x0.991 smd: 15(1.475,0.25)
ACES_50209-0060N-P01_6P
  oval 0.508x1.651 smd: 1(0,0) 2(0.8,0) 3(1.6,0) 4(2.4,0) 5(3.2,0) 6(4,0)
  rect 1.194x1.702 smd: 7(-1.3,-2.275) 8(5.3,-2.275)
ACES_50271-0020N-001_2P
  oval 0.787x1.6 smd: 1(0,0) 2(1.25,0)
  rect 2.108x2.997 smd: 3(3.8,-2.9) 4(-2.55,-2.9)
ACES_50271-0040N-001_4P
  oval 0.787x1.6 smd: 1(0,0) 2(-1.25,0) 3(-2.5,0) 4(-3.75,0)
  rect 2.108x2.997 smd: 5(2.55,-2.9) 6(-6.3,-2.9)
ACES_50398-04041-001_40P
  oval 0.254x1.295 smd: 1(0,0) 2(0.5,0) 3(1,0) 4(1.5,0) 5(2,0) 6(2.5,0) 7(3,0) 8(3.5,0) 9(4,0) 10(4.5,0) 11(5,0) 12(5.5,0) 13(6,0) 14(6.5,0) 15(7,0) 16(7.5,0) 17(8,0) 18(8.5,0) 19(9,0) 20(9.5,0) 21(10,0) 22(10.5,0) 23(11,0) 24(11.5,0) 25(12,0) 26(12.5,0) 27(13,0) 28(13.5,0) 29(14,0) 30(14.5,0) 31(15,0) 32(15.5,0) 33(16,0) 34(16.5,0) 35(17,0) 36(17.5,0) 37(18,0) 38(18.5,0) 39(19,0) 40(19.5,0)
  rect 1.194x3.2 smd: 41(-2.4,1.95) 45(21.9,1.95)
  rect 2.311x1.295 smd: 42(0.85,3.9) 43(9.75,3.9) 44(18.65,3.9)
ACES_50506-00641-P01_6P
  oval 0.305x0.889 smd: 1(0,0) 2(0.5,0) 3(1,0) 4(1.5,0) 5(2,0) 6(2.5,0)
  rect 0.991x2.007 smd: 7(-2.1,-3.05) 8(4.6,-3.05)
ACES_50506-01041-P01_10P
  oval 0.305x0.889 smd: 1(0,0) 2(0.5,0) 3(1,0) 4(1.5,0) 5(2,0) 6(2.5,0) 7(3,0) 8(3.5,0) 9(4,0) 10(4.5,0)
  rect 0.991x2.007 smd: 11(-2.1,-3.05) 12(6.6,-3.05)
ACES_50506-01841-P01_18P
  oval 0.305x0.889 smd: 1(0,0) 2(0.5,0) 3(1,0) 4(1.5,0) 5(2,0) 6(2.5,0) 7(3,0) 8(3.5,0) 9(4,0) 10(4.5,0) 11(5,0) 12(5.5,0) 13(6,0) 14(6.5,0) 15(7,0) 16(7.5,0) 17(8,0) 18(8.5,0)
  rect 0.991x2.007 smd: 19(-2.1,-3.05) 20(10.6,-3.05)
ACON_HMRBL-A41L0F_19P-T
  round 0.813 hole 0.559: 1(0,0) 2(0.5,1.55) 3(1,0) 4(1.5,1.55) 5(2,0) 6(2.5,1.55) 7(3,0) 8(3.5,1.55) 9(4,0) 10(4.5,1.55) 11(5,0) 12(5.5,1.55) 13(6,0) 14(6.5,1.55) 15(7,0) 16(7.5,1.55) 17(8,0) 18(8.5,1.55) 19(9,0)
  oval 1.397x2.21 hole 0.787x1.6: 20(11.75,0.2) 22(-2.75,0.2)
  oval 1.702x2.997 hole 1.092x2.388: 21(13.25,-8.15) 23(-4.25,-8.15)
ACON_TCRA2-9U1U93_9P-T
  round 1.295 hole 0.711: 1(0,0) 2(-2.5,0) 3(-4.5,0) 4(-7,0) 5(-7.5,-1.5) 6(-5.5,-1.5) 7(-3.5,-1.5) 8(-1.5,-1.5) 9(0.5,-1.5)
  oval 1.295x2.311 hole 0.711x1.702: 10(2.9,0.3) 12(-9.9,0.3)
  oval 1.295x2.007 hole 0.711x1.397: 11(4.2,-8.95) 13(-11.2,-8.95)
ALC3246-CG_MQFN48_6X6
  oval 0.889x0.203 smd: 1(0,0) 2(0,-0.4) 3(0,-0.8) 4(0,-1.2) 5(0,-1.6) 6(0,-2) 7(0,-2.4) 8(0,-2.8) 9(0,-3.2) 10(0,-3.6) 11(0,-4) 12(0,-4.4) 25(6.1,-4.4) 26(6.1,-4) 27(6.1,-3.6) 28(6.1,-3.2) 29(6.1,-2.8) 30(6.1,-2.4) 31(6.1,-2) 32(6.1,-1.6) 33(6.1,-1.2) 34(6.1,-0.8) 35(6.1,-0.4) 36(6.1,0)
  oval 0.203x0.889 smd: 13(0.85,-5.25) 14(1.25,-5.25) 15(1.65,-5.25) 16(2.05,-5.25) 17(2.45,-5.25) 18(2.85,-5.25) 19(3.25,-5.25) 20(3.65,-5.25) 21(4.05,-5.25) 22(4.45,-5.25) 23(4.85,-5.25) 24(5.25,-5.25) 37(5.25,0.85) 38(4.85,0.85) 39(4.45,0.85) 40(4.05,0.85) 41(3.65,0.85) 42(3.25,0.85) 43(2.85,0.85) 44(2.45,0.85) 45(2.05,0.85) 46(1.65,0.85) 47(1.25,0.85) 48(0.85,0.85)
  rect 4.394x4.394 smd: 49(3.05,-2.2)
ALPINE-RIDGE_BGA_337P
  round 0.254 smd: A1(0,0) A23(10.12,0) AA2(0.46,-9.2) AA22(9.66,-9.2) AB2(0.46,-9.66) AB3(0.92,-9.66) AB4(1.38,-9.66) AB5(1.84,-9.66) AB6(2.3,-9.66) AB7(2.76,-9.66) AB8(3.22,-9.66) AB9(3.68,-9.66) AB10(4.14,-9.66) AB11(4.6,-9.66) AB12(5.06,-9.66) AB13(5.52,-9.66) AB14(5.98,-9.66) AB15(6.44,-9.66) AB16(6.9,-9.66) AB17(7.36,-9.66) AB18(7.82,-9.66) AB19(8.28,-9.66) AB20(8.74,-9.66) AB21(9.2,-9.66) AB22(9.66,-9.66) AC1(0,-10.12) AC23(10.12,-10.12) B2(0.46,-0.46) B3(0.92,-0.46) B4(1.38,-0.46) B5(1.84,-0.46) B6(2.3,-0.46) B7(2.76,-0.46) B8(3.22,-0.46) B9(3.68,-0.46) B10(4.14,-0.46) B11(4.6,-0.46) B12(5.06,-0.46) B13(5.52,-0.46) B14(5.98,-0.46) B15(6.44,-0.46) B16(6.9,-0.46) B17(7.36,-0.46) B18(7.82,-0.46) B19(8.28,-0.46) B20(8.74,-0.46) B21(9.2,-0.46) B22(9.66,-0.46) C2(0.46,-0.92) C22(9.66,-0.92) D2(0.46,-1.38) D4(1.16,-1.16) D5(1.81,-1.16) D6(2.46,-1.16) D8(3.11,-1.16) D9(3.76,-1.16) D11(4.41,-1.16) D12(5.06,-1.16) D13(5.71,-1.16) D15(6.36,-1.16) D16(7.01,-1.16) D18(7.66,-1.16) D19(8.31,-1.16) D20(8.96,-1.16) D22(9.66,-1.38) E2(0.46,-1.84) E4(1.16,-1.81) E5(1.81,-1.81) E6(2.46,-1.81) E8(3.11,-1.81) E9(3.76,-1.81) E11(4.41,-1.81) E12(5.06,-1.81) E13(5.71,-1.81) E15(6.36,-1.81) E16(7.01,-1.81) E18(7.66,-1.81) E19(8.31,-1.81) E20(8.96,-1.81) E22(9.66,-1.84) F2(0.46,-2.3) F4(1.16,-2.46) F5(1.81,-2.46) F6(2.46,-2.46) F8(3.11,-2.46) F9(3.76,-2.46) F11(4.41,-2.46) F12(5.06,-2.46) F13(5.71,-2.46) F15(6.36,-2.46) F16(7.01,-2.46) F18(7.66,-2.46) F19(8.31,-2.46) F20(8.96,-2.46) F22(9.66,-2.3) G2(0.46,-2.76) G22(9.66,-2.76) H2(0.46,-3.22) H4(1.16,-3.11) H5(1.81,-3.11) H6(2.46,-3.11) H8(3.11,-3.11) H9(3.76,-3.11) H11(4.41,-3.11) H12(5.06,-3.11) H13(5.71,-3.11) H15(6.36,-3.11) H16(7.01,-3.11) H18(7.66,-3.11) H19(8.31,-3.11) H20(8.96,-3.11) H22(9.66,-3.22) J2(0.46,-3.68) J4(1.16,-3.76) J5(1.81,-3.76) J6(2.46,-3.76) J8(3.11,-3.76) J9(3.76,-3.76) J11(4.41,-3.76) J12(5.06,-3.76) J13(5.71,-3.76) J15(6.36,-3.76) J16(7.01,-3.76) J18(7.66,-3.76) J19(8.31,-3.76) J20(8.96,-3.76) J22(9.66,-3.68) K2(0.46,-4.14) K22(9.66,-4.14) L2(0.46,-4.6) L4(1.16,-4.41) L5(1.81,-4.41) L6(2.46,-4.41) L8(3.11,-4.41) L9(3.76,-4.41) L11(4.41,-4.41) L12(5.06,-4.41) L13(5.71,-4.41) L15(6.36,-4.41) L16(7.01,-4.41) L18(7.66,-4.41) L19(8.31,-4.41) L20(8.96,-4.41) L22(9.66,-4.6) M2(0.46,-5.06) M4(1.16,-5.06) M5(1.81,-5.06) M6(2.46,-5.06) M8(3.11,-5.06) M9(3.76,-5.06) M11(4.41,-5.06) M12(5.06,-5.06) M13(5.71,-5.06) M15(6.36,-5.06) M16(7.01,-5.06) M18(7.66,-5.06) M19(8.31,-5.06) M20(8.96,-5.06) M22(9.66,-5.06) N2(0.46,-5.52) N4(1.16,-5.71) N5(1.81,-5.71) N6(2.46,-5.71) N8(3.11,-5.71) N9(3.76,-5.71) N11(4.41,-5.71) N12(5.06,-5.71) N13(5.71,-5.71) N15(6.36,-5.71) N16(7.01,-5.71) N18(7.66,-5.71) N19(8.31,-5.71) N20(8.96,-5.71) N22(9.66,-5.52) P2(0.46,-5.98) P22(9.66,-5.98) R2(0.46,-6.44) R4(1.16,-6.36) R5(1.81,-6.36) R6(2.46,-6.36) R8(3.11,-6.36) R9(3.76,-6.36) R11(4.41,-6.36) R12(5.06,-6.36) R13(5.71,-6.36) R15(6.36,-6.36) R16(7.01,-6.36) R18(7.66,-6.36) R19(8.31,-6.36) R20(8.96,-6.36) R22(9.66,-6.44) T2(0.46,-6.9) T4(1.16,-7.01) T5(1.81,-7.01) T6(2.46,-7.01) T8(3.11,-7.01) T9(3.76,-7.01) T11(4.41,-7.01) T12(5.06,-7.01) T13(5.71,-7.01) T15(6.36,-7.01) T16(7.01,-7.01) T18(7.66,-7.01) T19(8.31,-7.01) T20(8.96,-7.01) T22(9.66,-6.9) U2(0.46,-7.36) U22(9.66,-7.36) V2(0.46,-7.82) V4(1.16,-7.66) V5(1.81,-7.66) V6(2.46,-7.66) V8(3.11,-7.66) V9(3.76,-7.66) V11(4.41,-7.66) V12(5.06,-7.66) V13(5.71,-7.66) V15(6.36,-7.66) V16(7.01,-7.66) V18(7.66,-7.66) V19(8.31,-7.66) V20(8.96,-7.66) V22(9.66,-7.82) W2(0.46,-8.28) W4(1.16,-8.31) W5(1.81,-8.31) W6(2.46,-8.31) W8(3.11,-8.31) W9(3.76,-8.31) W11(4.41,-8.31) W12(5.06,-8.31) W13(5.71,-8.31) W15(6.36,-8.31) W16(7.01,-8.31) W18(7.66,-8.31) W19(8.31,-8.31) W20(8.96,-8.31) W22(9.66,-8.28) Y2(0.46,-8.74) Y4(1.16,-8.96) Y5(1.81,-8.96) Y6(2.46,-8.96) Y8(3.11,-8.96) Y9(3.76,-8.96) Y11(4.41,-8.96) Y12(5.06,-8.96) Y13(5.71,-8.96) Y15(6.36,-8.96) Y16(7.01,-8.96) Y18(7.66,-8.96) Y19(8.31,-8.96) Y20(8.96,-8.96) Y22(9.66,-8.74)
  oval 0.178x0.33 smd: A2(0.46,0) A3(0.92,0) A4(1.38,0) A5(1.84,0) A6(2.3,0) A7(2.76,0) A8(3.22,0) A9(3.68,0) A10(4.14,0) A11(4.6,0) A12(5.06,0) A13(5.52,0) A14(5.98,0) A15(6.44,0) A16(6.9,0) A17(7.36,0) A18(7.82,0) A19(8.28,0) A20(8.74,0) A21(9.2,0) A22(9.66,0) AC2(0.46,-10.12) AC3(0.92,-10.12) AC4(1.38,-10.12) AC5(1.84,-10.12) AC6(2.3,-10.12) AC7(2.76,-10.12) AC8(3.22,-10.12) AC9(3.68,-10.12) AC10(4.14,-10.12) AC11(4.6,-10.12) AC12(5.06,-10.12) AC13(5.52,-10.12) AC14(5.98,-10.12) AC15(6.44,-10.12) AC16(6.9,-10.12) AC17(7.36,-10.12) AC18(7.82,-10.12) AC19(8.28,-10.12) AC20(8.74,-10.12) AC21(9.2,-10.12) AC22(9.66,-10.12)
  oval 0.33x0.178 smd: AA1(0,-9.2) AA23(10.12,-9.2) AB1(0,-9.66) AB23(10.12,-9.66) B1(0,-0.46) B23(10.12,-0.46) C1(0,-0.92) C23(10.12,-0.92) D1(0,-1.38) D23(10.12,-1.38) E1(0,-1.84) E23(10.12,-1.84) F1(0,-2.3) F23(10.12,-2.3) G1(0,-2.76) G23(10.12,-2.76) H1(0,-3.22) H23(10.12,-3.22) J1(0,-3.68) J23(10.12,-3.68) K1(0,-4.14) K23(10.12,-4.14) L1(0,-4.6) L23(10.12,-4.6) M1(0,-5.06) M23(10.12,-5.06) N1(0,-5.52) N23(10.12,-5.52) P1(0,-5.98) P23(10.12,-5.98) R1(0,-6.44) R23(10.12,-6.44) T1(0,-6.9) T23(10.12,-6.9) U1(0,-7.36) U23(10.12,-7.36) V1(0,-7.82) V23(10.12,-7.82) W1(0,-8.28) W23(10.12,-8.28) Y1(0,-8.74) Y23(10.12,-8.74)
AO6405_TSOP6
  oval 0.508x1.473 smd: 1(0,0) 2(0.95,0) 3(1.9,0) 4(1.9,2.35) 5(0.95,2.35) 6(0,2.35)
AON6992_DFN5X6D-8-7
  oval 0.66x0.635 smd: 1(0,0) 3(3.81,5.67) 4(2.54,5.67) 5(1.27,5.67) 6(0,5.67)
  custom 0.485x0.485 smd: 2(1.905,0.655)
  rect 3.988x2.667 smd: 7(1.905,3.62)
AON7409_DFN8-5
  oval 0.406x0.991 smd: 1(0,0) 2(0.66,0) 3(1.32,0) 4(1.98,0)
  custom 0.559x0.559 smd: 5(0.99,2.247)
AON7934_DFN3X3A8-10
  oval 0.457x0.508 smd: 1(0,0) 2(0.65,0) 3(1.3,0) 4(1.95,0) 5(1.95,2.76) 6(1.3,2.76) 7(0.65,2.76) 8(0,2.76)
  rect 2.54x1.041 smd: 9(0.975,1.813)
  rect 2.54x0.559 smd: 10(0.975,0.708)
AOZ1336_DFN8_2X2
  oval 0.254x0.787 smd: 1(0,0) 2(0.5,0) 3(1,0) 4(1.5,0) 5(1.5,2.2) 6(1,2.2) 7(0.5,2.2) 8(0,2.2)
  rect 1.499x0.889 smd: 9(0.75,1.1)
AP2112K-3P3TRG1_SOT23-5
  oval 0.508x0.965 smd: 1(0,0) 2(0.95,0) 3(1.9,0) 4(1.9,2.375) 5(0,2.375)
AP2204R-5P0TRG1_SOT89-3
  oval 0.889x1.295 smd: 1(0,0) 3(3,0)
  custom 0.433x0.433 smd: 2(1.5,1.775)
AP2204RA-3P3TRG1_SOT89-3
  oval 0.889x1.295 smd: 1(0,0) 3(3,0)
  custom 0.433x0.433 smd: 2(1.5,1.775)
AP2330W-7_SC59-3
  oval 0.787x0.991 smd: 1(0,0) 2(-0.95,-2.4) 3(0.95,-2.4)
AP7361C-FGE-7_U-DFN3030-8_3X3
  oval 0.457x0.94 smd: 1(0,0) 2(0.65,0) 3(1.3,0) 4(1.95,0) 5(1.95,3.05) 6(1.3,3.05) 7(0.65,3.05) 8(0,3.05)
  rect 2.261x1.499 smd: 9(0.975,1.525)
APX8131AI-TRG_SOT23-3
  oval 1.016x1.524 smd: 1(0,0) 2(0.965,2.083) 3(-0.965,2.083)
AZC199-02SPR7G_SOT23-3
  oval 1.016x1.524 smd: 1(0,0) 2(0.965,2.083) 3(-0.965,2.083)
BAT54CW_SOT323-3
  oval 0.711x0.889 smd: 1(0,0) 2(-0.65,-1.9) 3(0.65,-1.9)
BELLW_80149-3221_67P
  round 1.092 hole 1.092 unplated: (-0.75,-5.275)
  round 1.6 hole 1.6 unplated: (19.25,-5.275)
  oval 0.305x1.549 smd: 1(0,0) 2(0.25,-7.55) 3(0.5,0) 4(0.75,-7.55) 5(1,0) 6(1.25,-7.55) 7(1.5,0) 8(1.75,-7.55) 9(2,0) 10(2.25,-7.55) 11(2.5,0) 12(4.75,-7.55) 13(5,0) 14(5.25,-7.55) 15(5.5,0) 16(5.75,-7.55) 17(6,0) 18(6.25,-7.55) 19(6.5,0) 20(6.75,-7.55) 21(7,0) 22(7.25,-7.55) 23(7.5,0) 24(7.75,-7.55) 25(8,0) 26(8.25,-7.55) 27(8.5,0) 28(8.75,-7.55) 29(9,0) 30(9.25,-7.55) 31(9.5,0) 32(9.75,-7.55) 33(10,0) 34(10.25,-7.55) 35(10.5,0) 36(10.75,-7.55) 37(11,0) 38(11.25,-7.55) 39(11.5,0) 40(11.75,-7.55) 41(12,0) 42(12.25,-7.55) 43(12.5,0) 44(12.75,-7.55) 45(13,0) 46(13.25,-7.55) 47(13.5,0) 48(13.75,-7.55) 49(14,0) 50(14.25,-7.55) 51(14.5,0) 52(14.75,-7.55) 53(15,0) 54(15.25,-7.55) 55(15.5,0) 56(15.75,-7.55) 57(16,0) 58(16.25,-7.55) 59(16.5,0) 60(16.75,-7.55) 61(17,0) 62(17.25,-7.55) 63(17.5,0) 64(17.75,-7.55) 65(18,0) 66(18.25,-7.55) 67(18.5,0)
  rect 1.194x2.743 smd: 68(-1.1,-0.775) 69(19.6,-0.775)
C-K_26230A-8K1A-02_9P-T
  round 1.194 hole 0.711: 1(0,0) 2(-2.5,0) 3(-4.5,0) 4(-7,0) 5(-7.5,-1.5) 6(-5.5,-1.5) 7(-3.5,-1.5) 8(-1.5,-1.5) 9(0.5,-1.5)
  oval 1.295x2.388 hole 0.711x1.803: 10(2.9,-0.4) 11(4.2,-8.95) 12(-9.9,-0.4) 13(-11.2,-8.95)
C_0201
  rect 0.381x0.356 smd: 1(0,0) 2(0.584,0)
C_0402
  rect 0.508x0.559 smd: 1(0,0) 2(0.914,0)
C_0603
  rect 0.635x0.889 smd: 1(0,0) 2(1.397,0)
C_0805
  rect 0.813x1.397 smd: 1(0,0) 2(1.702,0)
C_1206
  rect 1.016x1.651 smd: 1(0,0) 2(2.667,0)
C_1808
  rect 1.041x2.311 smd: 1(0,0) 2(4.35,0)
C_B2
  rect 1.346x2.692 smd: 1(0,0) 2(-2.75,0)
C_D
  rect 2.388x2.896 smd: 1(0,0) 2(6.1,0)
C_D2
  rect 2.388x2.794 smd: 1(0,0) 2(6.4,0)
C_D3
  rect 2.388x2.794 smd: 1(0,0) 2(6.4,0)
CSD97374CQ4M_SON8_3P5X4P5
  oval 0.203x0.889 smd: 1(0,0) 2(0.4,0) 3(0.8,0) 6(0.8,3.5) 7(0.4,3.5) 8(0,3.5)
  custom 0.225x0.225 smd: 4(2.2,0.262) 5(2.2,3.238)
  rect 4.039x2.21 smd: 9(1.6,1.75)
CVILU_CF5020FD0RK-05-NH_20P-T
  oval 0.305x0.94 smd: 1(0,0) 2(0.5,0) 3(1,0) 4(1.5,0) 5(2,0) 6(2.5,0) 7(3,0) 8(3.5,0) 9(4,0) 10(4.5,0) 11(5,0) 12(5.5,0) 13(6,0) 14(6.5,0) 15(7,0) 16(7.5,0) 17(8,0) 18(8.5,0) 19(9,0) 20(9.5,0)
  rect 1.651x1.397 smd: 21(-2.325,-3.375) 22(11.825,-3.375)
CVILU_CF5026FD0RK-05-NH_26P-T
  oval 0.305x0.94 smd: 1(0,0) 2(0.5,0) 3(1,0) 4(1.5,0) 5(2,0) 6(2.5,0) 7(3,0) 8(3.5,0) 9(4,0) 10(4.5,0) 11(5,0) 12(5.5,0) 13(6,0) 14(6.5,0) 15(7,0) 16(7.5,0) 17(8,0) 18(8.5,0) 19(9,0) 20(9.5,0) 21(10,0) 22(10.5,0) 23(11,0) 24(11.5,0) 25(12,0) 26(12.5,0)
  rect 1.651x1.397 smd: 27(14.825,-3.375) 28(-2.325,-3.375)
CVILU_CI0805M1HRC-NH_5P-T
  round 1.803 hole 1.803 unplated: (-0.2,5.2) (8.2,5.2)
  oval 0.889x2.388 smd: 1(0,0) 2(2,0) 3(4,0) 4(6,0) 5(8,0)
  rect 1.6x2.489 smd: 6(11.15,9.05) 7(-3.15,9.05)
CVILU_CI1804M1VRA-NH_4P
  oval 0.508x0.991 smd: 1(0,-0.05) 2(-0.8,-0.05) 3(-1.6,-0.05) 4(-2.4,-0.05)
  rect 1.194x1.702 smd: 5(-3.7,1.4) 6(1.3,1.4)
CYNTE_PCMB063T-1R0MS_2P
  rect 2.362x3.505 smd: 1(0,0) 2(6.05,0)
CYNTE_PCMC063T-1R5MN_2P
  rect 2.159x3.505 smd: 1(0,0) 2(5.85,0)
DB3J315E0L_SMINI3-F2-B3
  oval 0.889x0.787 smd: 1(0,0) 2(-0.65,-1.9) 3(0.65,-1.9)
DDTA114EUA-7-F_SOT323-3
  oval 0.813x0.914 smd: 1(0,0) 2(0.65,1.6) 3(-0.65,1.6)
DEREN_40-42251-01001RHF_10P-T
  oval 0.838x2.21 smd: 1(0,0.1) 2(1.5,0.1) 3(3,0.1) 4(4.5,0.1) 5(6,0.1) 6(7.5,0.1) 7(9,0.1) 8(10.5,0.1) 9(12,0.1) 10(13.5,0.1)
  custom 0.75x0.75 smd: 11(-3.4,-3.15) 12(16.9,-3.15)
DMN65D8LDW-7_SOT363-6
  oval 0.432x0.61 smd: 1(0,0) 2(0.65,0) 3(1.3,0) 4(1.3,1.9) 5(0.65,1.9) 6(0,1.9)
DMN65D8LW-7_SOT323-3
  oval 0.711x0.889 smd: 1(0,0) 2(-0.65,-1.9) 3(0.65,-1.9)
DMN66D0LDW-7_SOT363-6
  oval 0.432x0.61 smd: 1(0,0) 2(0.65,0) 3(1.3,0) 4(1.3,1.9) 5(0.65,1.9) 6(0,1.9)
E-T_4251K-F06N-40L_6P
  oval 0.406x0.991 smd: 1(0,0) 2(0.6,0) 3(1.2,0) 4(1.8,0) 5(2.4,0) 6(3,0)
  rect 0.711x1.041 smd: 7(3.95,-1.575) 8(-0.95,-1.575)
E-T_6601K-Y61N-04L_61P
  oval 0.305x1.245 smd: 1(0,0) 3(0.6,0) 5(1.2,0) 7(1.8,0) 9(2.4,0) 11(3,0) 13(3.6,0) 15(4.2,0) 17(4.8,0) 19(5.4,0) 21(6,0) 23(6.6,0) 25(7.2,0) 27(7.8,0) 29(8.4,0) 31(9,0) 33(9.6,0) 35(10.2,0) 37(10.8,0) 39(11.4,0) 41(12,0) 43(12.6,0) 45(13.2,0) 47(13.8,0) 49(14.4,0) 51(15,0) 53(15.6,0) 55(16.2,0) 57(16.8,0) 59(17.4,0) 61(18,0)
  oval 0.305x0.94 smd: 2(0.3,3.25) 4(0.9,3.25) 6(1.5,3.25) 8(2.1,3.25) 10(2.7,3.25) 12(3.3,3.25) 14(3.9,3.25) 16(4.5,3.25) 18(5.1,3.25) 20(5.7,3.25) 22(6.3,3.25) 24(6.9,3.25) 26(7.5,3.25) 28(8.1,3.25) 30(8.7,3.25) 32(9.3,3.25) 34(9.9,3.25) 36(10.5,3.25) 38(11.1,3.25) 40(11.7,3.25) 42(12.3,3.25) 44(12.9,3.25) 46(13.5,3.25) 48(14.1,3.25) 50(14.7,3.25) 52(15.3,3.25) 54(15.9,3.25) 56(16.5,3.25) 58(17.1,3.25) 60(17.7,3.25)
  rect 0.305x1.143 smd: 62(-0.65,0.6) 63(18.65,0.6)
E-T_6705K-Y20N-00L_20P
  oval 0.305x1.092 smd: 1(0,0) 2(-0.5,0) 3(-1,0) 4(-1.5,0) 5(-2,0) 6(-2.5,0) 7(-3,0) 8(-3.5,0) 9(-4,0) 10(-4.5,0) 11(-5,0) 12(-5.5,0) 13(-6,0) 14(-6.5,0) 15(-7,0) 16(-7.5,0) 17(-8,0) 18(-8.5,0) 19(-9,0) 20(-9.5,0)
  rect 0.991x2.007 smd: 21(2.1,-3.15) 22(-11.6,-3.15)
EMIST_SUL-12A2M_1P
  rect 6.909x1.194 smd: 1(0,0)
ESD8011MUT5G_X3DFN2-2-S
  rect 0.33x0.356 smd: 1(0,0) 2(0.43,0)
FDV301N-G_SOT23-3
  oval 1.016x1.524 smd: 1(0,0) 2(0.965,2.083) 3(-0.965,2.083)
FIDUCIAL_C40M80
  round 1.016 smd: 1(0,0)
G524B1T11U_SOT23-5
  oval 0.533x1.194 smd: 1(0,0) 2(0.95,0) 3(1.9,0) 4(1.9,3) 5(0,3)
H_1P0N
  round 0.991 hole 0.991 unplated: (0,0)
H_2P3-G
  round 2.819 hole 2.311: 1(0,0)
H_2P5-G
  round 2.997 hole 2.489: 1(0,0)
H_2P5N
  round 2.489 hole 2.489 unplated: (0,0)
H_3P2
  round 3.708 hole 3.2: 1(0,0)
H_3P3
  round 3.81 hole 3.302: 1(0,0)
H_3P5X2P5-G
  oval 4.013x2.997 hole 3.505x2.489: 1(0,0)
H_3P5X2P5N
  oval 3.505x2.489 hole 3.505x2.489 unplated: (0,0)
H_3P7-G
  round 4.216 hole 3.708: 1(0,0)
H_4P7X3P7-G
  oval 5.207x4.216 hole 4.699x3.708: 1(0,0)
H_5P0X4P0-G
  oval 5.512x4.496 hole 5.004x3.988: 1(0,0)
